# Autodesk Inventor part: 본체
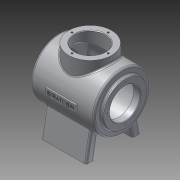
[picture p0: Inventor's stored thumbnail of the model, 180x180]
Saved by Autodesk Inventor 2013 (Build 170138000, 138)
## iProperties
Created: 2015-01
Part Number: 본체
Material: 알루미늄 6061
Document SubType Name: Modeling
Designer: Administrator
Density: 2.71 g/cm^3
Mass: 1021.43 g
Surface Area: 1058.43 cm^2
Volume: 376.91 cm^3
Author: Administrator
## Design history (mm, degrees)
sketch "스케치4"
  geometry: L1 (-62, -38)-(60, -38); L2 (60, -38)-(60, 38); L3 (60, 38)-(-62, 38); L4 (-62, 38)-(-62, -38); 2 further points
  constraints: 8 end point, 2 parallel, 1 horizontal, 1 horizontal alignment, 1 midpoint, 1 perpendicular
  dimensions: "d4" = 60 distance from line of L2 point (0, 0); "d5" = 122 distance of L1.start L1.end; "d6" = 76 distance of L3.end L1.start
extrude "돌출1" new body sketch "스케치4" stored distance "d7" = 76; taper "d8" = 0 deg
fillet "모깎기1" dims "d9" = 38
sketch "스케치5"
  geometry: L1 (-57, -50)-(55, -50); L2 (55, -50)-(55, 50); L3 (55, 50)-(-57, 50); L4 (-57, 50)-(-57, -50); L5 (-62, -38)-(-62, 38) reference; L6 (-62, 38)-(60, 38) reference; L7 (60, 38)-(60, -38) reference; L8 (60, -38)-(-62, -38) reference; 2 further points
  constraints: 8 end point, 2 parallel, 1 horizontal, 1 horizontal alignment, 1 midpoint, 1 perpendicular
  dimensions: "d10" = 112 distance of L1.start L1.end; "d12" = 100 distance of L1.end L2.end; "d13" = 5 distance between parallel lines of L5 L4
extrude "돌출2" join sketch "스케치5" stored distance "d14" = 100; taper "d15" = 0 deg
fillet "모깎기2" dims "d16" = 50
node "작업 평면1"
sketch "스케치7"
  geometry: C1 r 45 at (0, 0); 1 further point
  constraints: 1 centre point, 1 coincident
  dimensions: "d22" = 90 diameter of C1
extrude "돌출3" cut sketch "스케치7" distance "d23" = 97; taper "d24" = 0 deg
node "작업 평면2"
sketch "스케치8"
  geometry: L1 (-60, -38)-(-60, 38) reference; C1 r 38 at (0, 0); 1 further point
  constraints: 1 centre point, 1 coincident
  dimensions: "d26" = 76 diameter of C1
extrude "돌출4" join sketch "스케치8" stored distance "d27" = 97; taper "d28" = 0 deg
fillet "모깎기3" dims "d29" = 3
sketch "스케치9"
  geometry: C1 r 27 at (0, 0); 1 further point
  constraints: 1 centre point, 1 coincident
  dimensions: "d30" = 54 diameter of C1
extrude "돌출5" cut sketch "스케치9" stored distance "d31" = 97; taper "d32" = 0 deg
sketch "스케치10"
  geometry: C1 r 27 at (0, 0); 1 further point
  constraints: 1 centre point, 1 coincident
  dimensions: "d33" = 54 diameter of C1
extrude "돌출6" cut sketch "스케치10" stored distance "d34" = 97; taper "d35" = 0 deg
sketch "스케치11"
  geometry: 2 further points
  constraints: 1 vertical alignment
  dimensions: "d36" = 32 distance of point (0, 0) point (0, 32)
hole "구멍1" sketch "스케치11" at (0, 32) diameter "d37" = 3.242; stored, may be unused: countersink angle "d41" = 90 deg, drill point angle "d43" = 118 deg; dims "d38" = 8, "d39" = 4, "d40" = 2, "d42" = 10
node "작업 평면3"
sketch "스케치12"
  geometry: 2 further points
  constraints: 1 vertical alignment
  dimensions: "d47" = 32 distance of point (0, 0) point (0, 32)
hole "구멍2" sketch "스케치12" at (0, 32) diameter "d48" = 3.242; stored, may be unused: countersink angle "d52" = 90 deg, drill point angle "d54" = 118 deg; dims "d49" = 8, "d50" = 4, "d51" = 2, "d53" = 10
sketch "스케치13"
  geometry: L1 (27.282, -41.901)-(34, -80); L2 (34, -80)-(48, -80); L3 (48, -80)-(39.336, -30.865); A1 r 50 centre (0, 0) between (39.336, -30.865) and (27.282, -41.901) reference; 1 further point
  constraints: 6 end point, 2 point on circle, 1 horizontal, 1 parallel
  dimensions: "d58" = 80 distance from line of L2 point (0, 0); "d59" = 100 deg angle of L2 L3; "d60" = 14 distance of L1.end L2.end; "d61" = 48 horizontal distance of point (0, 0) L2.end
extrude "돌출7" join sketch "스케치13" stored distance "d62" = 80; taper "d63" = 0 deg
fillet "모깎기4" dims "d64" = 3
fillet "모깎기5" dims "d65" = 3
chamfer "모따기1" distance "d66" = 1; stored, may be unused: second distance "d67" = 2, angle "d68" = 45 deg
node "작업 평면5"
sketch "스케치19"
  geometry: L1 (-27, -6)-(27, -6); L2 (27, -6)-(27, 6); L3 (27, 6)-(-27, 6); L4 (-27, 6)-(-27, -6); 3 further points
  constraints: 8 end point, 2 midpoint, 2 parallel, 1 horizontal, 1 horizontal alignment, 1 perpendicular, 1 vertical alignment
  dimensions: "d77" = 54 distance of L2.end L3.end; "d79" = 12 distance of L3.end L1.start
extrude "돌출9" join sketch "스케치19" stored distance "d80" = 80; taper "d81" = 0 deg
sketch "스케치20"
  geometry: 2 further points
  constraints: 1 coincident, 1 other
feature "엠보싱2" sketch "스케치20" dims "d4" = 60, "d5" = 122, "d6" = 76, "d82" = 0.5, "d83" = 0
node "솔리드1"
pattern_circular "원형 패턴1" dims angle "d45" = 360 deg
mirror "대칭1"
pattern_circular "원형 패턴2" dims angle "d56" = 360 deg
mirror "대칭2"
node "절단 모서리 투영1"
other parameters: "d21" = -12, "d25" = 62, "d76" = -52
